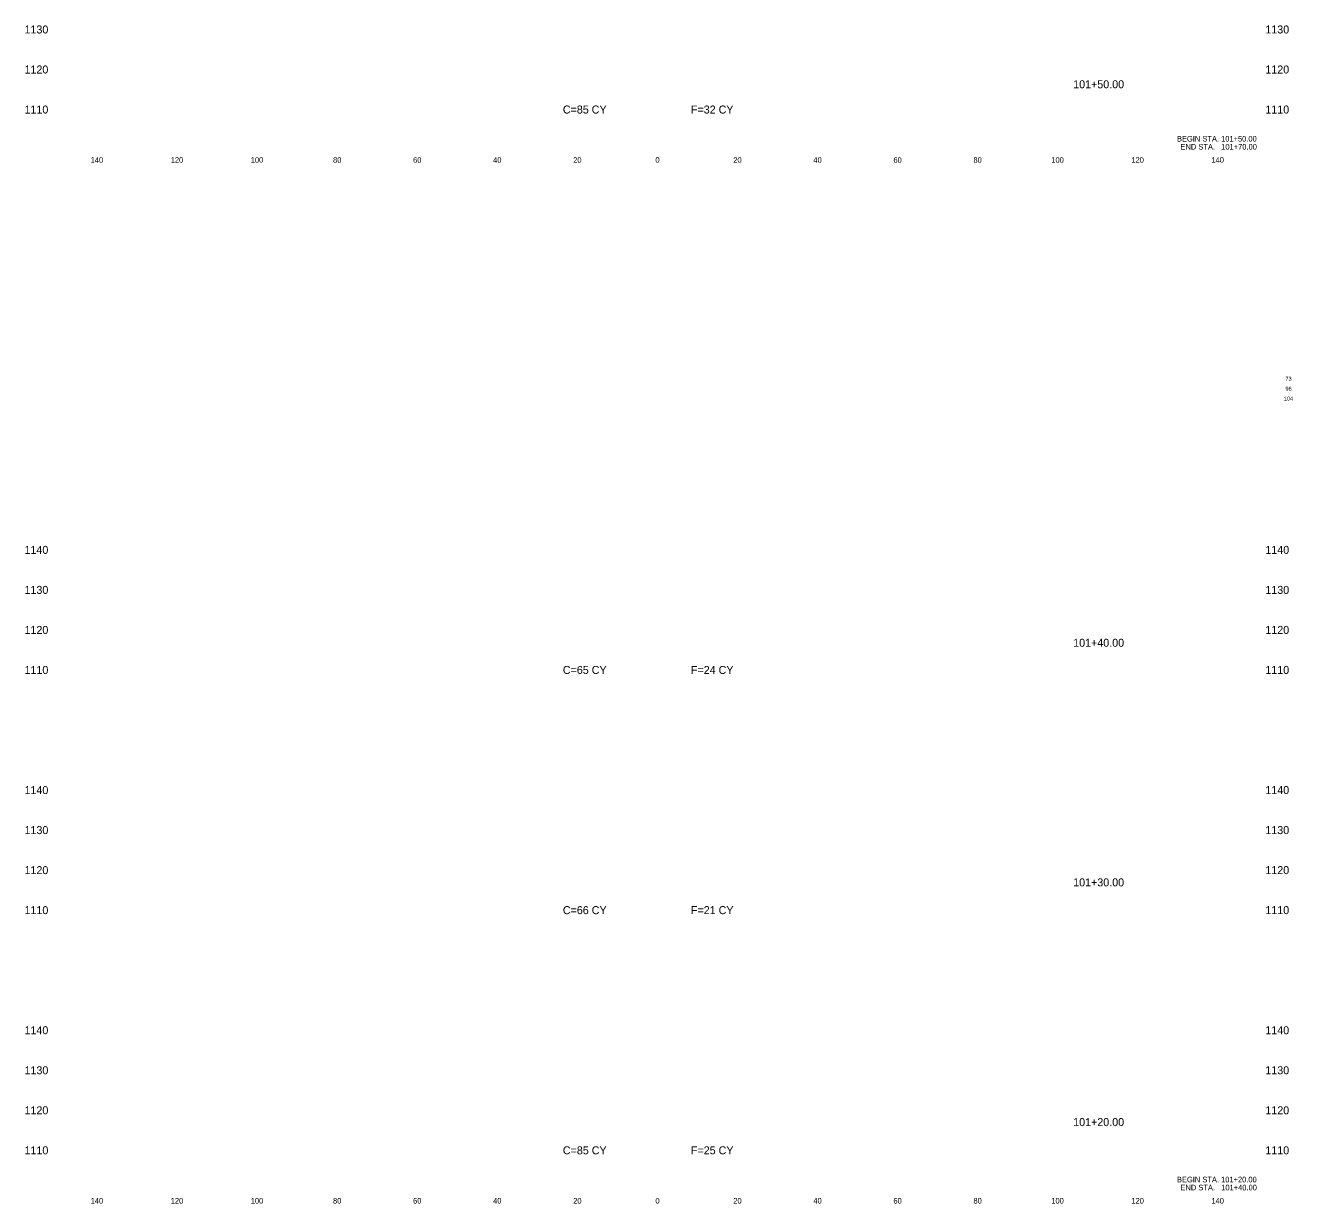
# Model space of a CAD drawing. Extents: x -200 to 1319, y -200 to 2499.
# Drawn here: x 1001.9 to 1318.5, y 1517.7 to 1812 of the extents above; entities that cross this region are included whole.
import ezdxf

# ---------------------------------------------------------------- set-up
doc = ezdxf.new("R2010")
doc.units = 0
for name, color, linetype in [('Default', 7, 'Continuous'), ('DESIGN - SHEET - Corner Text', 7, 'Continuous'), ('DESIGN - TYPICAL - Text', 7, 'Continuous')]:
    doc.layers.add(name, color=color, linetype=linetype)

msp = doc.modelspace()

# ---------------------------------------------------------------- texts
at = {"layer": 'Default'}
for s, height, p in [('     1130     ', 2, (998.01, 1810)), ('     1130     ', 2, (1308.01, 1810)), ('     1120     ', 2, (998.01, 1800)), ('     1120     ', 2, (1308.01, 1800)), ('     101+50.00     ', 2, (1260, 1796.31)), ('     1110     ', 2, (998.01, 1790)), ('     1110     ', 2, (1308.01, 1790)), ('     140     ', 1.4, (1015.65, 1777.7)), ('     120     ', 1.4, (1035.65, 1777.7)), ('     100     ', 1.4, (1055.65, 1777.7)), ('     80     ', 1.4, (1076.2, 1777.7)), ('     60     ', 1.4, (1096.2, 1777.7)), ('     40     ', 1.4, (1116.2, 1777.7)), ('     20     ', 1.4, (1136.2, 1777.7)), ('     0     ', 1.4, (1156.74, 1777.7)), ('     0     ', 1.4, (1156.74, 1777.7)), ('     20     ', 1.4, (1176.2, 1777.7)), ('     40     ', 1.4, (1196.2, 1777.7)), ('     60     ', 1.4, (1216.2, 1777.7)), ('     80     ', 1.4, (1236.2, 1777.7)), ('     100     ', 1.4, (1255.65, 1777.7)), ('     120     ', 1.4, (1275.65, 1777.7)), ('     140     ', 1.4, (1295.65, 1777.7)), ('     1140     ', 2, (998.01, 1680)), ('     1140     ', 2, (1308.01, 1680)), ('     1130     ', 2, (998.01, 1670)), ('     1130     ', 2, (1308.01, 1670)), ('     1120     ', 2, (998.01, 1660)), ('     1120     ', 2, (1308.01, 1660)), ('     101+40.00     ', 2, (1260, 1656.79)), ('     1110     ', 2, (998.01, 1650)), ('     1110     ', 2, (1308.01, 1650)), ('     1140     ', 2, (998.01, 1620)), ('     1140     ', 2, (1308.01, 1620)), ('     1130     ', 2, (998.01, 1610)), ('     1130     ', 2, (1308.01, 1610)), ('     1120     ', 2, (998.01, 1600)), ('     101+30.00     ', 2, (1260, 1596.94)), ('     1120     ', 2, (1308.01, 1600)), ('     1110     ', 2, (998.01, 1590)), ('     1110     ', 2, (1308.01, 1590)), ('     1140     ', 2, (998.01, 1560)), ('     1140     ', 2, (1308.01, 1560)), ('     1130     ', 2, (998.01, 1550)), ('     1130     ', 2, (1308.01, 1550)), ('     1120     ', 2, (998.01, 1540)), ('     1120     ', 2, (1308.01, 1540)), ('     101+20.00     ', 2, (1260, 1537.06)), ('     1110     ', 2, (998.01, 1530)), ('     1110     ', 2, (1308.01, 1530)), ('     140     ', 1.4, (1015.65, 1517.7)), ('     120     ', 1.4, (1035.65, 1517.7)), ('     100     ', 1.4, (1055.65, 1517.7)), ('     80     ', 1.4, (1076.2, 1517.7)), ('     60     ', 1.4, (1096.2, 1517.7)), ('     40     ', 1.4, (1116.2, 1517.7)), ('     20     ', 1.4, (1136.2, 1517.7)), ('     0     ', 1.4, (1156.74, 1517.7)), ('     0     ', 1.4, (1156.74, 1517.7)), ('     20     ', 1.4, (1176.2, 1517.7)), ('     40     ', 1.4, (1196.2, 1517.7)), ('     60     ', 1.4, (1216.2, 1517.7)), ('     80     ', 1.4, (1236.2, 1517.7)), ('     100     ', 1.4, (1255.65, 1517.7)), ('     120     ', 1.4, (1275.65, 1517.7)), ('     140     ', 1.4, (1295.65, 1517.7))]:
    msp.add_text(s, height=height, dxfattribs=at).set_placement(p)
at = {"layer": 'DESIGN - SHEET - Corner Text'}
for s, height, p in [('BEGIN STA. 101+50.00', 1.4, (1289.64, 1783)), ('END STA.   101+70.00', 1.4, (1290.51, 1781)), ('73', 1, (1316.75, 1723.25)), ('104', 1, (1316.35, 1718.31)), ('96', 1, (1316.75, 1720.75)), ('BEGIN STA. 101+20.00', 1.4, (1289.64, 1523)), ('END STA.   101+40.00', 1.4, (1290.51, 1521))]:
    msp.add_text(s, height=height, dxfattribs=at).set_placement(p)
at = {"layer": 'DESIGN - TYPICAL - Text'}
for s, p in [('C=85 CY', (1136.22, 1790)), ('F=32 CY', (1168.22, 1790)), ('C=65 CY', (1136.22, 1650)), ('F=24 CY', (1168.22, 1650)), ('C=66 CY', (1136.22, 1590)), ('F=21 CY', (1168.22, 1590)), ('C=85 CY', (1136.22, 1530)), ('F=25 CY', (1168.22, 1530))]:
    msp.add_text(s, height=2, dxfattribs=at).set_placement(p)

doc.saveas('drawing.dxf')
